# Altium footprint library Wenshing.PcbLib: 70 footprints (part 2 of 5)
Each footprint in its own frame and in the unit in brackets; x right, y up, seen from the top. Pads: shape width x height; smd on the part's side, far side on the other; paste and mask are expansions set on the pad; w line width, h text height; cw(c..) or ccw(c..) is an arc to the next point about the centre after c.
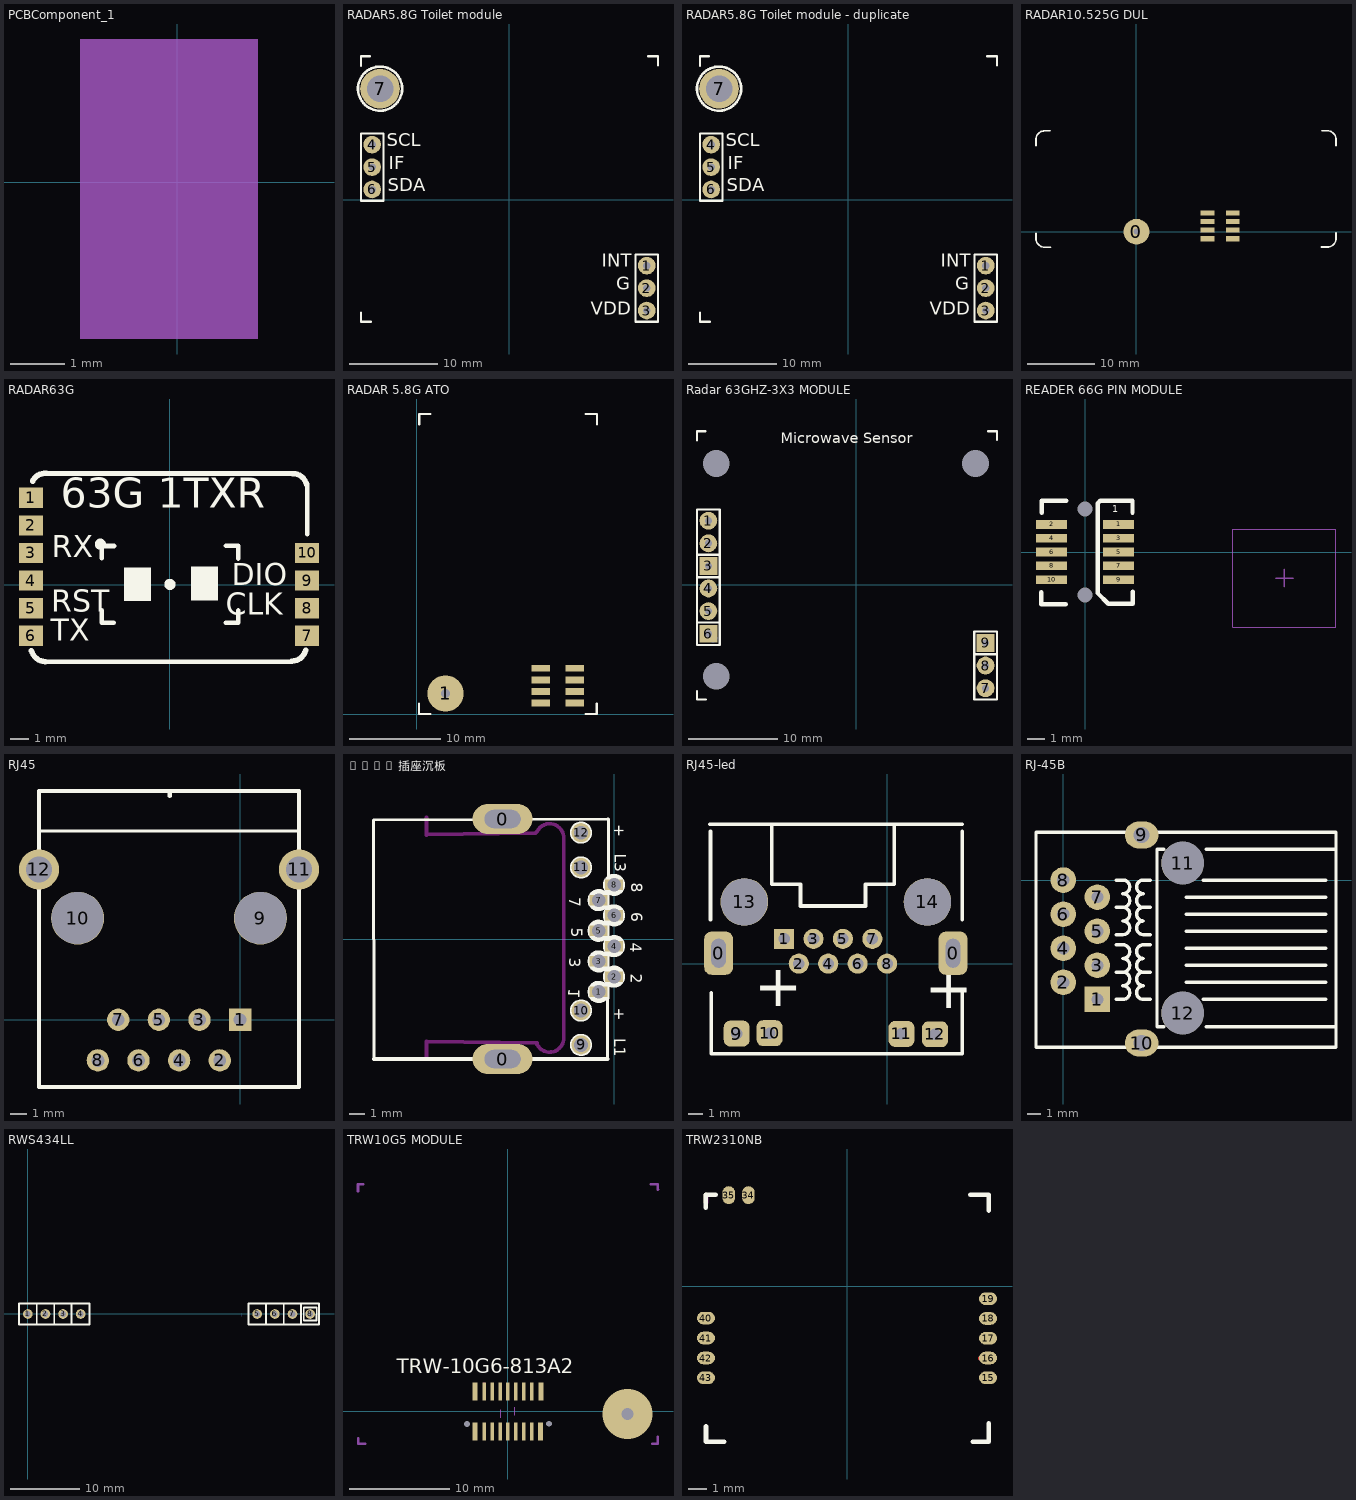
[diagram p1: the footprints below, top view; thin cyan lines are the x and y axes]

## PCBComponent_1 [mm]
Mechanical 2:
  rectangle: -1.778,-2.87 1.473,2.616
3D body "實驗電源 .step": height 18.76, standoff -24.74, extent -44.012,-5.074 16.495,37.182

## RADAR5.8G Toilet module [mil]
pads (7):
  round 78.74 hole 32 mask+4: 1(612.5,-295) 2(612.5,-395) 3(612.5,-495) 4(-612.5,245) 5(-612.5,145) 6(-612.5,45)
  round 177.17 / inner round 177.17 / far side round 78.74 hole 118.11: 7(-577.5,495)
Top Overlay:
  circle w11.81: c-577.5,495 r98.43
  lines w10: -662.2,-505.28 -662.2,-545.28 -619.2,-545.28 ; -662.2,596.72 -662.2,639.72 -622.2,639.72 ; 619.8,639.72 662.8,639.72 662.8,599.72 ; 622.8,-545.28 662.8,-545.28 662.8,-502.28 ; -662.5,-5 -662.5,295 -562.5,295 -562.5,-5 -662.5,-5 ; 562.5,-545 562.5,-245 662.5,-245 662.5,-545 562.5,-545
  text "SCL" at -548.2,218.72 h100
  text "IF" at -539.2,115.72 h100
  text "SDA" at -544.2,16.72 h100
  text "INT" at 412.8,-319.28 h100
  text "G" at 475.8,-422.28 h100
  text "VDD" at 361.8,-533.28 h100
3D body: height 118.11, standoff 0, extent -642.46,430.04 -512.54,559.96

## RADAR5.8G Toilet module - duplicate [mil]
pads (7):
  round 78.74 hole 32 mask+4: 1(612.5,-295) 2(612.5,-395) 3(612.5,-495) 4(-612.5,245) 5(-612.5,145) 6(-612.5,45)
  round 177.17 / inner round 177.17 / far side round 78.74 hole 118.11: 7(-577.5,495)
Top Overlay:
  circle w11.81: c-577.5,495 r98.43
  lines w10: -662.2,-505.28 -662.2,-545.28 -619.2,-545.28 ; -662.2,596.72 -662.2,639.72 -622.2,639.72 ; 619.8,639.72 662.8,639.72 662.8,599.72 ; 622.8,-545.28 662.8,-545.28 662.8,-502.28 ; -662.5,-5 -662.5,295 -562.5,295 -562.5,-5 -662.5,-5 ; 562.5,-545 562.5,-245 662.5,-245 662.5,-545 562.5,-545
  text "SCL" at -548.2,218.72 h100
  text "IF" at -539.2,115.72 h100
  text "SDA" at -544.2,16.72 h100
  text "INT" at 412.8,-319.28 h100
  text "G" at 475.8,-422.28 h100
  text "VDD" at 361.8,-533.28 h100
3D body: height 118.11, standoff 0, extent -642.46,430.04 -512.54,559.96

## RADAR10.525G DUL [mm]
pads (9):
  round 3.81 / inner round 1.2 / far side round 1.2 hole 0.9 mask+0.152: 0(0,0)
  rect 2.05x0.76 smd: 1(14.217,2.776) 2(10.467,2.776) 3(14.217,1.506) 4(10.467,1.506) 5(14.217,0.236) 6(10.467,0.236) 7(14.217,-1.034) 8(10.467,-1.034)
Top Overlay:
  lines w0.254: -14.836,-0.232 -14.836,-1.021 ccw(c-13.566,-1.021) -13.566,-2.291 -12.679,-2.291 ; -14.834,12.738 -14.834,13.625 cw(c-13.564,13.625) -13.564,14.895 -12.775,14.895 ; 27.307,-2.261 28.194,-2.261 ccw(c28.194,-0.991) 29.464,-0.991 29.464,-0.202 ; 27.402,14.9 28.191,14.9 cw(c28.191,13.63) 29.461,13.63 29.461,12.743
3D body: height 2.9, standoff 0, extent -1.805,-1.795 1.795,1.805
3D body "Connector 8pin 1.27mm.stp": height 1.4, standoff -5, extent 10.771,-1.905 14.021,3.585
3D body: height 3, standoff 0, extent -1.009,-1.03 0.991,0.97

## RADAR63G [mm] "RADAR 63GHZ MODULE 10M"
pads (10):
  rect 1.3x1.1 smd mask+0: 1(-7.55,4.725) 2(-7.55,3.225) 3(-7.55,1.725) 4(-7.55,0.225) 5(-7.55,-1.275) 6(-7.55,-2.775) 7(7.45,-2.775) 8(7.45,-1.275) 9(7.45,0.225) 10(7.45,1.725)
Top Layer:
  lines w0.127: -7.55,-1.275 -7.536,-1.289
  lines w0.152: -7.55,-2.775 -7.281,-2.506 ; -7.55,1.725 -7.221,1.396
  lines w0.25: -7.55,4.725 -7.543,4.718
Top Overlay:
  circle w0.3: c-3.783,2.202 r0.15
  circle w0.3: c0.002,0.018 r0.15
  circle w0.3: c0.002,0.018 r0.15
  rectangle: -2.5,-0.896 -1.025,0.929
  rectangle: 1.15,-0.846 2.625,0.979
  lines w0.254: -6.772,-4.178 6.628,-4.178 ; -6.722,6.044 6.703,6.044 ; -3.706,-1.379 -3.706,-2.065 -3.046,-2.065 ; -3.706,1.44 -3.706,2.101 -3.021,2.101 ; 3.025,-2.065 3.71,-2.065 3.71,-1.404 ; 3.05,2.114 3.71,2.114 3.71,1.428 ; 7.428,5.444 7.453,5.444 7.453,2.744
  lines w0.3: -7.522,-3.581 ccw(c-6.759,-3.393) -6.772,-4.178 ; -7.464,5.627 cw(c-6.81,5.332) -6.722,6.044 ; 6.628,-4.153 ccw(c6.616,-3.368) 7.378,-3.556 ; 6.678,6.042 cw(c6.666,5.257) 7.428,5.444
  text "63G 1TXR" at -5.925,3.631 h2.8
  text "TX" at -6.472,-3.456 h2.03
  text "RX" at -6.422,1.094 h2.03
  text "CLK" at 3.025,-2.044 h2.03
  text "DIO" at 3.353,-0.434 h2.03
  text "RST" at -6.45,-1.879 h2.03
3D body "RADER 60 1T1R DCDC.step": height 1.8, standoff -0.07, extent -7.614,-4.374 7.602,6.167
3D body: height 0.8, standoff 0, extent -3.573,-1.932 3.577,1.968

## RADAR 5.8G ATO [mm]
pads (9):
  round 4 / inner round 4 / far side round 1.5 hole 1 mask+0.102: 1(3.142,2.255)
  rect 2.05x0.76 smd: 1(17.359,5.031) 2(13.609,5.031) 3(17.359,3.761) 4(13.609,3.761) 5(17.359,2.491) 6(13.609,2.491) 7(17.359,1.221) 8(13.609,1.221)
Top Overlay:
  lines w0.254: 0.229,1.13 0.229,0 1.46,0 ; 0.254,31.864 0.254,32.995 1.486,32.995 ; 18.555,0 19.787,0 19.787,1.13 ; 18.567,32.995 19.799,32.995 19.799,31.864
Bottom Overlay:
  circle w0.3: c3.142,2.255 r1.2
3D body: height 4.5, standoff 0, extent 16.42,4.655 17.22,5.455
3D body: height 4.5, standoff 0, extent 16.42,3.38 17.22,4.18
3D body: height 4.5, standoff 0, extent 16.47,2.105 17.27,2.905
3D body: height 4.5, standoff 0, extent 16.445,0.855 17.245,1.655
3D body: height 4.5, standoff 0, extent 13.57,0.855 14.37,1.655
3D body: height 4.5, standoff 0, extent 13.545,2.13 14.345,2.93
3D body: height 4.5, standoff 0, extent 13.545,3.405 14.345,4.205
3D body: height 4.5, standoff 0, extent 13.57,4.655 14.37,5.455
3D body: height 1.5, standoff 0, extent 13.335,0.203 17.628,6.121
3D body: height 5.3, standoff 0, extent 0.808,-0.079 5.475,4.588

## Radar 63GHZ-3X3 MODULE [mm]
pads (12):
  round 0 hole 3: 0(-15.709,-10.274)
  round 0 hole 3 unplated: 0(-15.709,13.602) 0(13.374,13.602)
  round 2 hole 0.813: 1(-16.598,7.188) 2(-16.598,4.648) 4(-16.598,-0.419) 5(-16.598,-2.959) 7(14.517,-11.608) 8(14.517,-9.068)
  rect 2x2 hole 0.813: 3(-16.598,2.108) 6(-16.598,-5.499) 9(14.517,-6.528)
Bottom Layer:
  lines w1: -16.598,-5.499 -16.098,-5.999
Top Overlay:
  circle w0.3: c-15.709,13.602 r1.281
  circle w0.3: c13.374,13.602 r1.281
  circle w0.3: c-15.709,-10.274 r1.281
  lines w0.254: -17.875,-11.925 -17.875,-12.875 -16.875,-12.875 ; -17.875,16.225 -17.875,17.225 -16.925,17.225 ; -17.868,-4.229 -15.328,-4.229 ; -17.868,3.378 -15.328,3.378 ; 13.247,-7.798 15.787,-7.798 ; 14.8,17.225 15.8,17.225 15.8,16.275 ; -17.868,-6.769 -17.868,0.851 -15.328,0.851 -15.328,-6.769 -17.868,-6.769 ; -17.868,0.838 -15.328,0.838 -15.328,8.458 -17.868,8.458 -17.868,0.838 ; 13.247,-12.878 13.247,-5.258 15.787,-5.258 15.787,-12.878 13.247,-12.878
  text "Microwave Sensor" at -8.47,15.507 h2.03
3D body "HEADER 3.STEP": height 10.23, standoff -1.37, extent 13.374,-12.801 15.914,-5.181
3D body "HEADER 3.STEP": height 10.23, standoff -1.37, extent -17.995,0.762 -15.455,8.382
3D body "HEADER 3.STEP": height 10.23, standoff -1.37, extent -17.995,-6.845 -15.455,0.775

## READER 66G PIN MODULE [mm] "66GHZ RF MODULE 2X8 0.8MM"
pads (12):
  round 0 hole 0.87 unplated mask+0.43: 0(0,-2.5) 0(0,2.5)
  rect 1.8x0.5 smd: 1(1.95,1.6) 2(-1.95,1.6) 3(1.95,0.8) 4(-1.95,0.8) 5(1.95,0) 6(-1.95,0) 7(1.95,-0.8) 8(-1.95,-0.8) 9(1.95,-1.6) 10(-1.95,-1.6)
Top Overlay:
  lines w0.254: -2.55,-2.325 -2.55,-3.025 -1.125,-3.025 ; -2.525,2.275 -2.525,2.975 -1.1,2.975 ; 2.75,2.275 2.75,2.975 1.325,2.975 0.875,2.975 0.725,2.825 0.725,-2.375 1.35,-3 2.775,-3 2.775,-2.3
  text "1" at 1.575,2.175 h0.7
Bottom Overlay:
  lines w0.254: -1.075,-1.6 1.825,-1.6
Bottom Courtyard:
  lines w0.05: 8.567,-4.365 14.567,-4.365 14.567,1.335 8.567,1.335 8.567,-4.365
  lines w0.1: 11.067,-1.515 12.067,-1.515 ; 11.567,-2.015 11.567,-1.015
3D body: height 5.1, standoff 0, extent -2.55,-3.025 2.775,2.95
3D body "66GHZ A121 PIN MODULE.step": height 16.71, standoff -0.33, extent -0.612,-5.356 4.475,5.255

## RFID TM1PORT [mm]
3D body "RFIDBY RF2 sky ldo.step": height 8, standoff 0.8, extent -44.617,-9.629 9.92,38.697

## RJ45 [mil]
pads (12):
  rect 55x55 hole 31.5: 1(0,0)
  round 55 hole 31.5: 2(-50,-100) 3(-100,0) 4(-150,-100) 5(-200,0) 6(-250,-100) 7(-300,0) 8(-350,-100)
  round 130 hole 127.95 unplated: 9(50,250) 10(-400,250)
  round 98.42 hole 62.99: 11(145,370) 12(-495,370)
Top Overlay:
  lines w8: -488.19,464.57 141.73,464.57
  lines w10: -495,-165.35 144.65,-165.35 145,-165 145,370 145,562.99 -495,562.99 -495,370 -495,-165 ; -173.23,551.18 -173.23,559.06
3D body "Mod-Jack-K122449007-Stig-W.STEP": height 127.85, standoff -555.12, extent -490,-172.17 139.92,556.17

## rj45 插座沉板 [mm] "https://item.taobao.com/item.htm?spm=a230r.1.14.1.2e43bdf9DXnvS9&id=570547930869&ns=1&abbucket=2#detail"
pads (14):
  oval 4x2 hole 1.2 slot 2.4 at 0 deg: 0(-7.429,-8) 0(-7.429,8)
  rect 1.2x0.7 hole 0.9: 1(-1.029,-3.53) 2(0,-2.51) 3(-1.029,-1.49) 4(0,-0.47) 5(-1.029,0.55) 6(0,1.57) 7(-1.029,2.59) 8(0,3.61)
  round 1.27 hole 0.914: 9(-2.2,-7.06) 10(-2.2,-4.77) 11(-2.2,4.77) 12(-2.2,7.09)
Top Overlay:
  circle w0.4: c-2.2,-7.06 r0.539
  circle w0.4: c-2.2,-4.77 r0.539
  circle w0.4: c-1.029,-3.53 r0.539
  circle w0.4: c0,-2.51 r0.539
  circle w0.4: c-1.029,-1.49 r0.539
  circle w0.4: c0,-0.47 r0.539
  circle w0.4: c-1.029,0.55 r0.539
  circle w0.4: c0,1.57 r0.539
  circle w0.4: c-1.029,2.59 r0.539
  circle w0.4: c0,3.61 r0.539
  circle w0.4: c-2.2,4.77 r0.539
  circle w0.4: c-2.2,7.09 r0.539
  lines w0.203: -15.992,-8 -16.05,7.94 -0.439,8 ; -0.439,-8 -0.384,8
  lines w0.254: -15.992,-8 -0.439,-8
  text "1" at -2.3,-3.3 h0.76
  text "2" at 1.1,-2.325 h0.76
  text "3" at -3,-1.25 h0.76
  text "4" at 1.075,-0.25 h0.76
  text "5" at -2.85,0.75 h0.76
  text "6" at 1.15,1.775 h0.76
  text "7" at -2.975,2.8 h0.76
  text "8" at 1.15,3.75 h0.76
  text "L1" at 0,-6.63 h0.76
  text "+" at 0,-4.59 h0.76
  text "L3" at 0.05,5.7 h0.76
  text "+" at 0,7.65 h0.76
Keep-Out Layer:
  lines w0.254: -12.5,6.94 -12.5,8.1 ; -12.499,-7.999 -12.499,-6.839 -5.129,-6.931 ; -12.498,6.977 -5.227,7.068 ; -5.129,-7.03 ccw(c-4.29,-6.611) -3.356,-6.536 -3.356,6.676 ccw(c-4.29,6.751) -5.129,7.17
3D body "rj45 ACC-M-RJE71-188-1X0X-REVT1.STEP": height 9.45, standoff -3.51, extent -20.274,-10.1 0.426,10.04

## RJ45-led [mm]
pads (16):
  rrect50% 2x3 hole 2 slot 1 at 0 deg: 0(-11.68,0.724) 0(4.576,0.724)
  rect 1.397x1.397 hole 0.8: 1(-7.14,1.718)
  round 1.397 hole 0.8: 2(-6.12,0) 3(-5.1,1.718) 4(-4.08,0) 5(-3.06,1.718) 6(-2.04,0) 7(-1.02,1.718) 8(0,0)
  rrect50% 1.8x1.8 hole 0.8: 9(-10.425,-4.85) 10(-8.15,-4.825) 11(1,-4.875) 12(3.325,-4.9)
  round 3.302 hole 3.25 unplated: 13(-9.902,4.28) 14(2.798,4.28)
Top Overlay:
  lines w0.254: -12.275,9.675 5.2,9.675 ; -12.24,3.06 -12.24,9.18 ; -12.188,-2.04 -12.188,-6.261 5.211,-6.261 5.211,-2.04 ; -8,9.675 -8,5.5 -6,5.5 -6,4 -1.5,4 -1.5,5.5 0.5,5.5 0.5,9.5 ; 5.211,3.06 5.211,9.18
  text "+" at -9.2,-3.925 h5
  text "+" at 2.625,-4.05 h5
Bottom Overlay:
  lines w0.254: -7.225,-0.775 -7.225,0.325 -6.675,0.875 -6.15,0.875 0.775,0.875 ; -6.125,1 -6.125,3.225 ; -5.125,-0.825 -5.125,0.75 ; -4.1,0.875 -4.1,2.7 ; -3.025,-0.9 -3.025,0.825 ; -2,0.875 -2,2.6 ; -1.025,-0.725 -1.025,0.825
Bottom Solder:
  circle w0.7: c-5.1,1.7 r0.407
  circle w0.7: c-3.05,1.75 r0.407
  circle w0.7: c-1.025,1.75 r0.407
  circle w0.7: c0,0.025 r0.407
  circle w0.7: c-2.025,0 r0.407
  circle w0.7: c-4.075,-0.025 r0.407
  circle w0.7: c-6.125,-0.025 r0.407
  rectangle: -12.775,-0.875 -10.6,2.325
  rectangle: 3.5,-0.875 5.675,2.325
  rectangle: 0.15,-6 1.85,-3.75
  rectangle: 2.475,-6.025 4.175,-3.775
  rectangle: -8.975,-5.95 -7.3,-3.7
  rectangle: -11.25,-5.95 -9.575,-3.7
  rectangle: -7.925,0.925 -6.35,2.5
3D body "rj45-led.stp": height 3.23, standoff -14.2, extent -12.306,-6.208 5.202,9.742

## RJ-45B [mm]
pads (12):
  rect 1.905x1.905 hole 0.9: 1(2.54,-8.89)
  round 1.905 hole 0.9: 2(0,-7.62) 3(2.54,-6.35) 4(0,-5.08) 5(2.54,-3.81) 6(0,-2.54) 7(2.54,-1.27) 8(0,0)
  oval 2.5x2 hole 1.2: 9(5.84,3.36) 10(5.84,-12.14)
  round 3.175 hole 3.175: 11(8.89,1.27) 12(8.89,-9.906)
Top Overlay:
  lines w0.254: 3.937,-8.89 4.445,-8.89 ccw(c4.445,-8.382) 4.445,-7.874 ccw(c4.445,-7.366) 4.445,-6.858 ; 3.937,-6.858 4.445,-6.858 ; 3.937,-4.826 4.445,-4.826 cw(c4.445,-5.334) 4.445,-5.842 cw(c4.445,-6.35) 4.445,-6.858 ; 3.937,-4.064 4.445,-4.064 ccw(c4.445,-3.556) 4.445,-3.048 ccw(c4.445,-2.54) 4.445,-2.032 ; 3.937,-2.032 4.445,-2.032 ; 3.937,0 4.445,0 cw(c4.445,-0.508) 4.445,-1.016 cw(c4.445,-1.524) 4.445,-2.032 ; 6.477,-8.89 5.969,-8.89 cw(c5.969,-8.382) 5.969,-7.874 cw(c5.969,-7.366) 5.969,-6.858 ; 6.477,-6.858 5.969,-6.858 ; 6.477,-4.826 5.969,-4.826 ccw(c5.969,-5.334) 5.969,-5.842 ccw(c5.969,-6.35) 5.969,-6.858 ; 6.477,-4.064 5.969,-4.064 cw(c5.969,-3.556) 5.969,-3.048 cw(c5.969,-2.54) 5.969,-2.032 ; 6.477,-2.032 5.969,-2.032 ; 6.477,0 5.969,0 ccw(c5.969,-0.508) 5.969,-1.016 ccw(c5.969,-1.524) 5.969,-2.032 ; 7.493,-10.922 6.985,-10.922 6.985,2.286 7.493,2.286 ; 9.144,-7.62 19.558,-7.62 ; 9.144,-6.35 19.558,-6.35 ; 9.144,-5.08 19.558,-5.08 ; 9.144,-3.81 19.558,-3.81 ; 9.144,-2.54 19.558,-2.54 ; 9.144,-1.27 19.558,-1.27 ; 10.414,-8.89 13.716,-8.89 19.558,-8.89 ; 10.414,0 13.462,0 19.558,0 ; 10.668,-10.922 17.272,-10.922 20.32,-10.922 ; 10.668,2.286 17.272,2.286 20.32,2.286 ; -2.032,-12.446 -1.524,-12.446 17.272,-12.446 20.32,-12.446 20.32,3.556 17.272,3.556 -1.524,3.556 -2.032,3.556 -2.032,-12.446

## RWS434LL [mm] "RF MODULE OOK"
pads (8):
  round 1.4 hole 0.8 mask+0.102: 1(0,0) 2(2.54,0) 3(5.08,0) 4(7.62,0) 5(33.045,0) 6(35.585,0) 7(38.125,0) 8(40.665,0)
Bottom Layer:
  region: 30.759,0 30.759,-0.318
  region: 30.759,0 30.759,-0.318
  region: 30.759,0 30.759,-0.318
  region: 30.759,0 30.759,-0.318
Top Overlay:
  lines w0.254: 1.27,-1.524 1.27,1.524 ; 3.81,-1.524 3.81,1.524 ; 6.301,-1.524 6.301,1.524 ; 34.315,-1.524 34.315,1.524 ; 36.855,-1.524 36.855,1.524 ; 39.322,1.524 39.346,1.524 39.346,-1.524 ; -1.27,-1.524 -1.27,1.524 8.89,1.524 8.89,-1.524 -1.27,-1.524 ; 31.775,-1.524 41.935,-1.524 41.935,1.524 31.775,1.524 31.775,-1.524 ; 39.751,-0.94 39.751,0.94 41.604,0.94 41.58,-0.94 39.751,-0.94
Bottom Overlay:
  lines w0.254: -1.255,-1.5 -1.255,1.5 8.945,1.5 ; 1.287,-1.5 1.287,1.5 ; 3.845,-1.5 3.845,1.5 ; 6.336,-1.5 6.336,1.5 ; 31.745,-1.5 31.745,1.5 41.945,1.5 41.945,-1.2 ; 34.287,1.5 34.345,1.5 34.345,-1.5 ; 36.845,-1.5 36.845,1.5 ; 39.359,-1.5 39.359,1.5
3D body "RWS-434LL.step": height 12, standoff -7.39, extent -1.412,-1.727 42.153,3.282

## TRW10G5 MODULE [mm]
pads (20):
  round 0 hole 0.6: 0(-4.096,-1.25) 0(4.096,-1.237)
  rect 0.5x1.8 smd: 1(3.275,-2) 9(-3.275,-2) 10(-3.275,1.975) 18(3.3,2)
  rect 0.35x1.8 smd: 2(2.409,-2) 3(1.609,-2) 4(0.809,-2) 5(0.009,-2) 6(-0.791,-2) 7(-1.591,-2) 8(-2.391,-2) 11(-2.391,2) 12(-1.591,2) 13(-0.791,2) 14(0.009,2) 15(0.809,2) 16(1.609,2) 17(2.409,2)
via 11.99,-0.251 diameter 5 hole 1.2
Top Layer:
  lines w0.203: -2.414,1.732 -2.414,2.811
Top Overlay:
  text "TRW-10G6-813A2" at -11.12,3.337 h2.5
Mechanical 1:
  lines w0.254: -15.008,22.019 -15.008,22.745 -14.469,22.745 -14.469,22.755 ; -15.005,-2.708 -14.995,-2.708 -14.995,-3.247 -14.269,-3.247 ; 14.289,22.754 15.016,22.754 15.016,22.215 15.025,22.215 ; 14.466,-3.255 14.466,-3.245 15.004,-3.245 15.004,-2.519
Mechanical 15:
  lines w0.025: -0.696,-0.654 -0.696,0.146 ; 0.684,-0.372 0.684,0.428
3D body: height 3, standoff 0, extent -3.189,-0.515 3.41,0.584
3D body: height 3, standoff 0, extent -4.285,-2.249 4.756,-1.295
3D body: height 3, standoff 0, extent -4.222,-1.308 4.819,2.136
3D body "TRW-10G6-813A2.step": height -3, standoff -7.46, extent -14.975,-3.197 15.025,22.798

## TRW2310NB [mm]
pads (11):
  oval 1x0.7 smd mask+0.05: 15(7.849,-5.081) 16(7.849,-3.981) 17(7.849,-2.881) 18(7.849,-1.781) 19(7.849,-0.681) 40(-7.849,-1.759) 41(-7.849,-2.869) 42(-7.849,-3.981) 43(-7.849,-5.081)
  oval 0.7x1 smd mask+0.05: 34(-5.486,5.081) 35(-6.582,5.081)
Top Layer:
  lines w0.305: 7.453,-3.981 7.849,-3.981
Top Overlay:
  lines w0.254: -7.872,4.38 -7.872,5.105 -7.297,5.105 ; -7.847,-7.77 -7.847,-8.645 -6.822,-8.645 ; 6.853,5.105 7.878,5.105 7.878,4.23 ; 7.003,-8.645 7.878,-8.645 7.878,-7.62
Keep-Out Layer:
  lines w0.254: -7.849,4.675 -7.849,5.107
3D body "TRW2310NB.step": height 2.27, standoff -0.01, extent -7.761,-8.6 7.961,5.166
